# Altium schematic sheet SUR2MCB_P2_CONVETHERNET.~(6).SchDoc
size 420 x 297 mm; Scale: 1:1; Разраб.: Иванов; Обозначение документа: АБВГ.123456.001 Э3; Пров.: Петров; Утв.: Сидоров; Наименование организации: ОАО "Концерн "МПО-Гидроприбор"; Перв. применение: АБВГ.123456.000; Наименование изделия 1: Плата; Наименование изделия 2: Схема электрическая; Наименование изделия 3: принципиальная; Нач. отд.: Нач. отд.; Фамилия нач. отд.: Сидоров
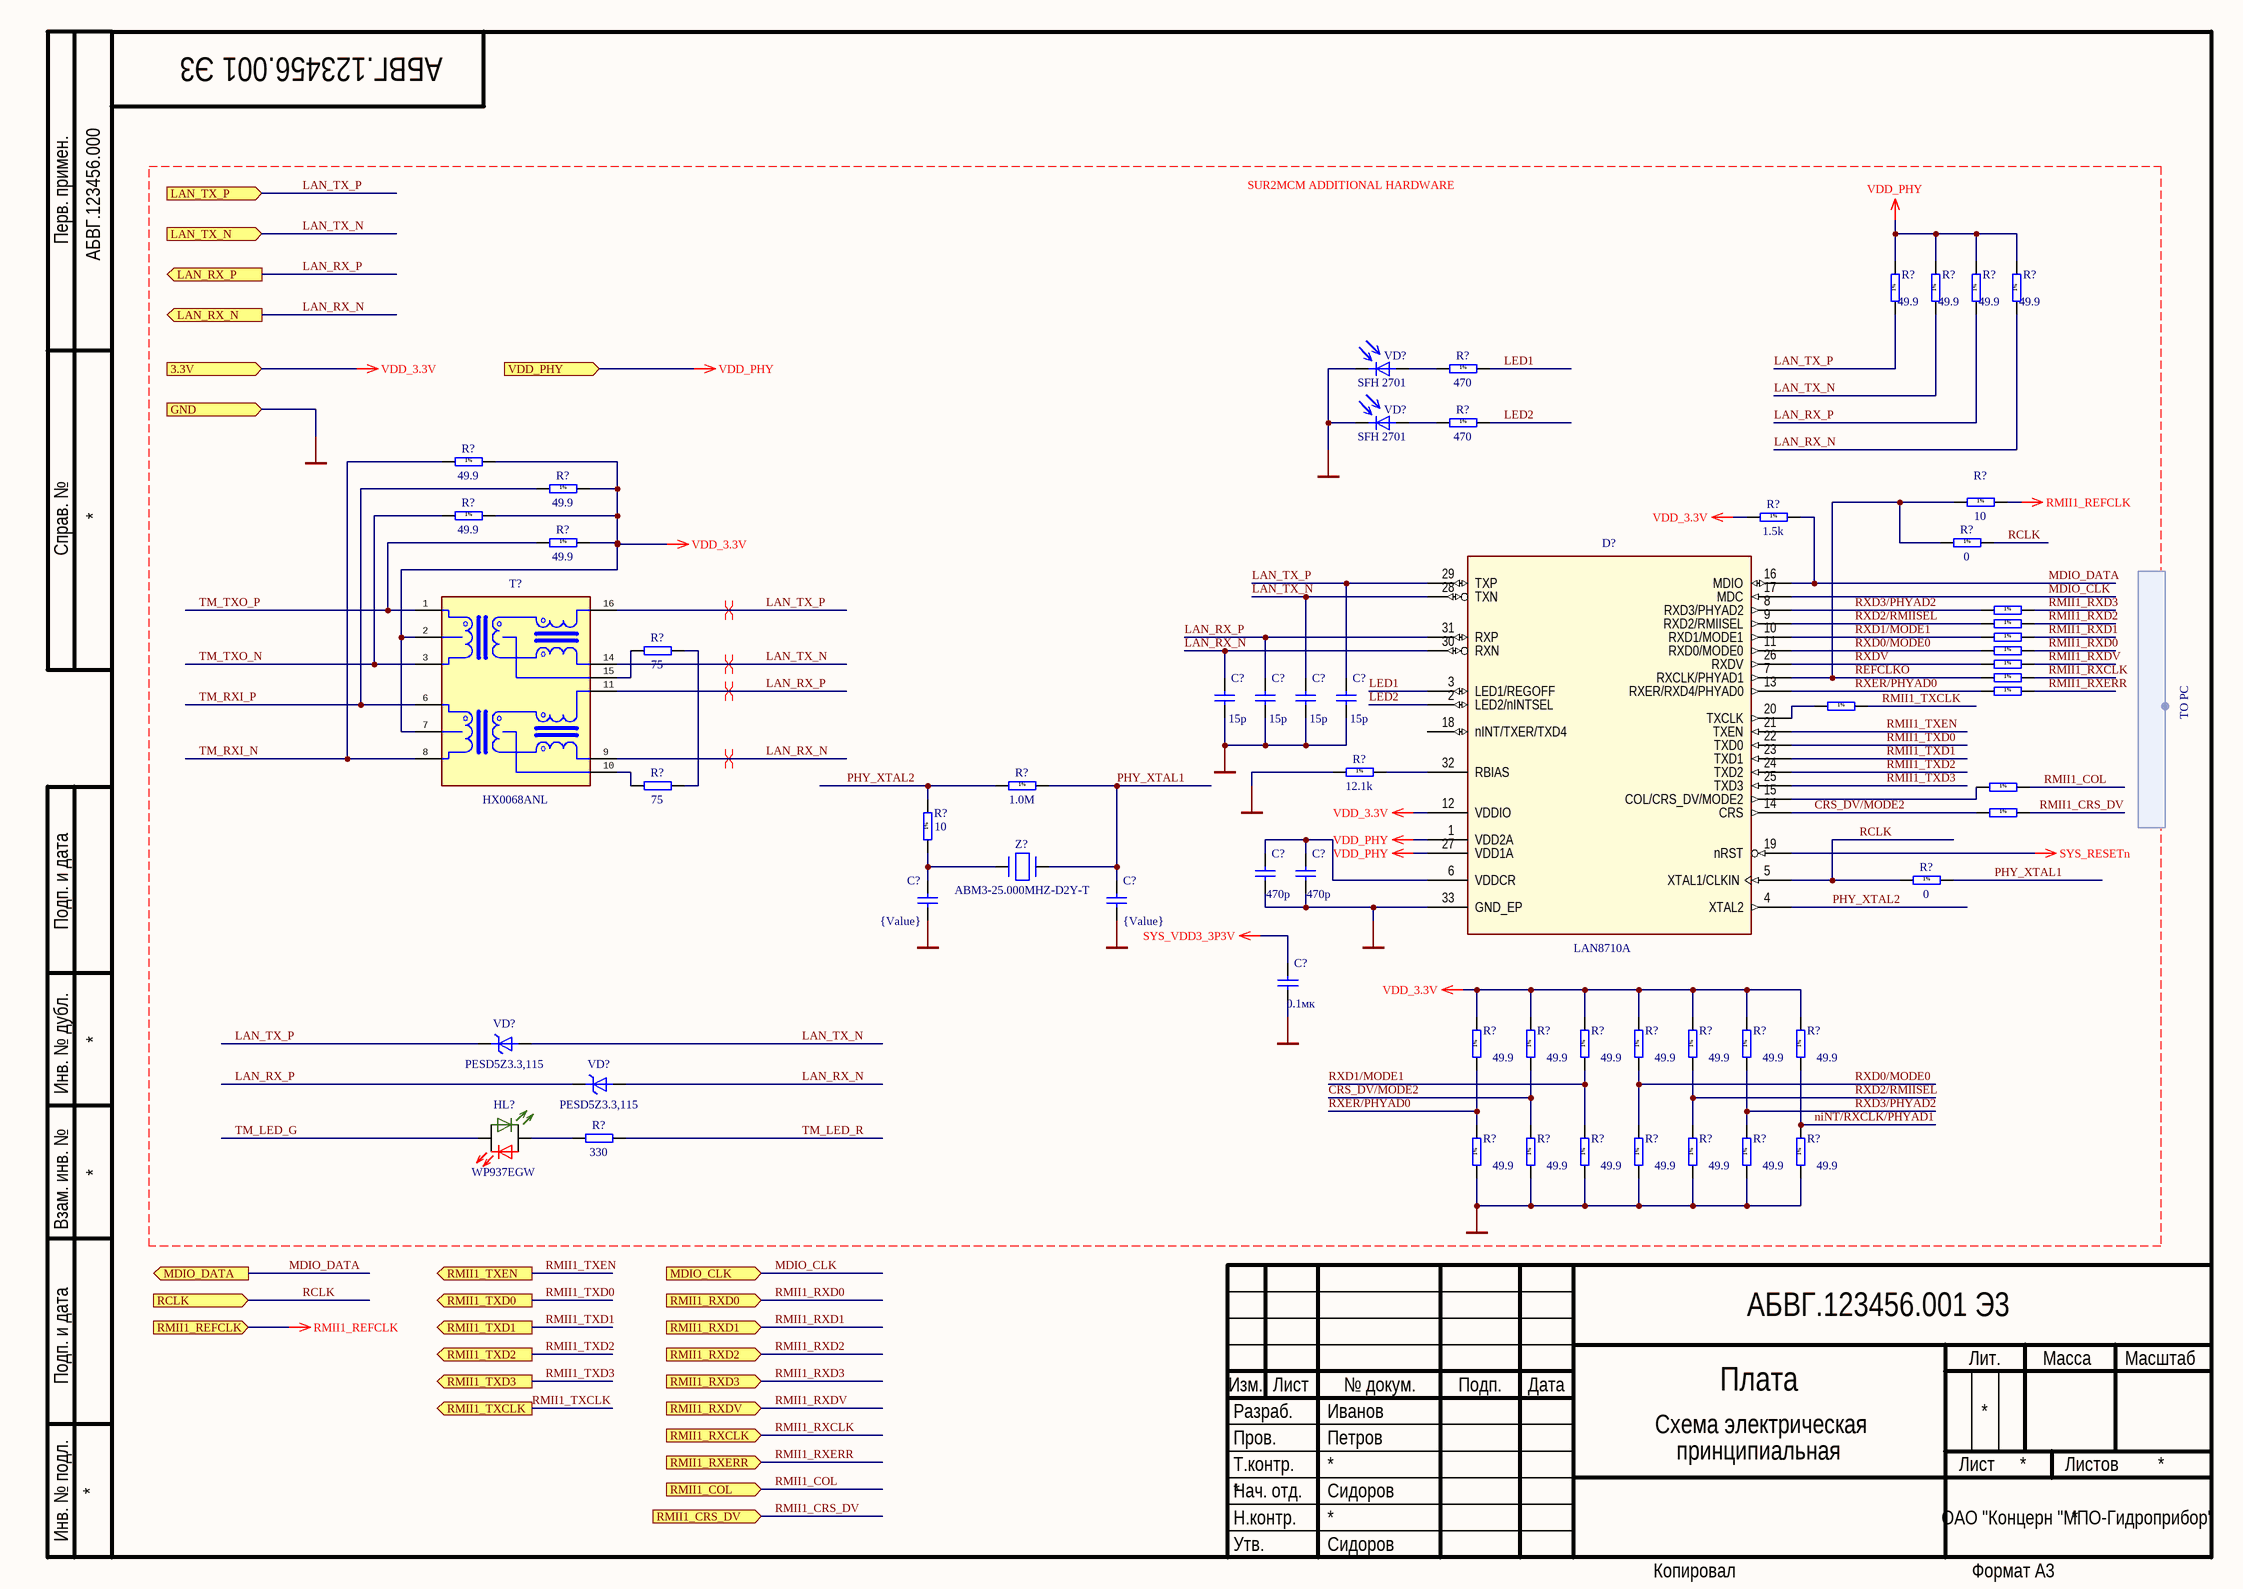
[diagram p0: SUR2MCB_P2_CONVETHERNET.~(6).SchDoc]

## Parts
(Parts that share a designator on the sheet are numbered #1, #2 ... from top to bottom, then left to right.)
C?#1  value 15p  [C0603]
C?#2  value 15p  [C0603]
C?#3  value 15p  [C0603]
C?#4  value 15p  [C0603]
C?#5  value 470p  [C0603]
C?#6  value 470p  [C0603]
C?#7  value {Value}  [C0603]
C?#8  value {Value}  [C0603]
C?#9  value 0.1мк  [C0603]
D?  value LAN8710A  [QFN-32-5X5-0.5-T]
HL?  value WP937EGW  [LED_3MM_ROUND]
R?#1  value 49.9  [R0603]
R?#2  value 49.9  [R0603]
R?#3  value 49.9  [R0603]
R?#4  value 49.9  [R0603]
R?#5  value 470  [R0603]
R?#6  value 470  [R0603]
R?#7  value 49.9  [R0603]
R?#8  value 49.9  [R0603]
R?#9  value 10  [R0603]
R?#10  value 49.9  [R0603]
R?#11  value 1.5k  [R0603]
R?#12  value 49.9  [R0603]
R?#13  value 0  [R0603]
R?#14  (no value)  [R0603]
R?#15  (no value)  [R0603]
R?#16  (no value)  [R0603]
R?#17  value 75  [R0603]
R?#18  (no value)  [R0603]
R?#19  (no value)  [R0603]
R?#20  (no value)  [R0603]
R?#21  (no value)  [R0603]
R?#22  (no value)  [R0603]
R?#23  value 12.1k  [R0603]
R?#24  value 75  [R0603]
R?#25  value 1.0М  [R0603]
R?#26  (no value)  [R0603]
R?#27  (no value)  [R0603]
R?#28  value 10  [R0603]
R?#29  value 0  [R0603]
R?#30  value 49.9  [R0603]
R?#31  value 49.9  [R0603]
R?#32  value 49.9  [R0603]
R?#33  value 49.9  [R0603]
R?#34  value 49.9  [R0603]
R?#35  value 49.9  [R0603]
R?#36  value 49.9  [R0603]
R?#37  value 330  [R0603]
R?#38  value 49.9  [R0603]
R?#39  value 49.9  [R0603]
R?#40  value 49.9  [R0603]
R?#41  value 49.9  [R0603]
R?#42  value 49.9  [R0603]
R?#43  value 49.9  [R0603]
R?#44  value 49.9  [R0603]
T?  value HX0068ANL  [HX0068ANL]
VD?#1  value SFH 2701  [SFH 2701]
VD?#2  value SFH 2701  [SFH 2701]
VD?#3  value PESD5Z3.3,115  [SOD-523]
VD?#4  value PESD5Z3.3,115  [SOD-523]
Z?  value ABM3-25.000MHZ-D2Y-T  [Crystal_2-SMD_(5.0X3.2)]

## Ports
3.3V (in), GND (in), LAN_RX_N (out), LAN_RX_P (out), LAN_TX_N (in), LAN_TX_P (in), MDIO_CLK (in), MDIO_DATA (out), RCLK (in), RMII1_COL (in), RMII1_CRS_DV (in), RMII1_REFCLK (in), RMII1_RXCLK (in), RMII1_RXD0 (in), RMII1_RXD1 (in), RMII1_RXD2 (in), RMII1_RXD3 (in), RMII1_RXDV (in), RMII1_RXERR (in), RMII1_TXCLK (out), RMII1_TXD0 (out), RMII1_TXD1 (out), RMII1_TXD2 (out), RMII1_TXD3 (out), RMII1_TXEN (out), VDD_PHY (in)

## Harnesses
TO PC: 

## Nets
GND: C?#1.1 C?#2.1 C?#3.1 C?#4.1 C?#5.1 C?#6.1 C?#7.1 C?#8.1 C?#9.1 D?.33(GND_EP) R?#23.2 R?#38.2 R?#39.2 R?#40.2 R?#41.2 R?#42.2 R?#43.2 R?#44.2 VD?#1.1(С) VD?#2.1(С) ; port GND
RMII1_REFCLK: R?#9.1 ; port RMII1_REFCLK
SYS_RESETn: D?.19(nRST)
SYS_VDD3_3P3V: C?#9.2
VDD_3.3V: D?.12(VDDIO) R?#7.1 R?#8.1 R?#10.1 R?#11.2 R?#12.1 R?#30.1 R?#31.1 R?#32.1 R?#33.1 R?#34.1 R?#35.1 R?#36.1 T?.2 T?.7 ; port 3.3V
VDD_PHY: D?.1(VDD2A) D?.27(VDD1A) R?#1.1 R?#2.1 R?#3.1 R?#4.1 ; port VDD_PHY
CRS_DV/MODE2: D?.14(CRS) R?#27.2 R?#31.2 R?#39.1
LAN_RX_N: C?#1.2 D?.30(RXN) R?#4.2 T?.9 VD?#4.2 ; port LAN_RX_N
LAN_RX_P: C?#2.2 D?.31(RXP) R?#3.2 T?.11 VD?#4.1 ; port LAN_RX_P
LAN_TX_N: C?#3.2 D?.28(TXN) R?#2.2 T?.14 VD?#3.2 ; port LAN_TX_N
LAN_TX_P: C?#4.2 D?.29(TXP) R?#1.2 T?.16 VD?#3.1 ; port LAN_TX_P
LED1: D?.3(LED1/REGOFF) R?#5.1
LED2: D?.2(LED2/nINTSEL) R?#6.1
MDIO_CLK: D?.17(MDC) ; port MDIO_CLK
MDIO_DATA: D?.16(MDIO) R?#11.1 ; port MDIO_DATA
niNT/RXCLK/PHYAD1: R?#36.2 R?#44.1
PHY_XTAL1: C?#8.2 R?#25.1 R?#29.1 Z?.2
PHY_XTAL2: D?.4(XTAL2) R?#25.2 R?#28.1
RCLK: D?.5(XTAL1/CLKIN) R?#13.1 R?#29.2 ; port RCLK
REFCLKO: D?.7(RXCLK/PHYAD1) R?#9.2 R?#13.2 R?#20.2
RMII1_COL: R?#26.1 ; port RMII1_COL
RMII1_CRS_DV: R?#27.1 ; port RMII1_CRS_DV
RMII1_RXCLK: R?#20.1 ; port RMII1_RXCLK
RMII1_RXD0: R?#18.1 ; port RMII1_RXD0
RMII1_RXD1: R?#16.1 ; port RMII1_RXD1
RMII1_RXD2: R?#15.1 ; port RMII1_RXD2
RMII1_RXD3: R?#14.1 ; port RMII1_RXD3
RMII1_RXDV: R?#19.1 ; port RMII1_RXDV
RMII1_RXERR: R?#21.1 ; port RMII1_RXERR
RMII1_TXCLK: R?#22.1 ; port RMII1_TXCLK
RMII1_TXD0: D?.22(TXD0) ; port RMII1_TXD0
RMII1_TXD1: D?.23(TXD1) ; port RMII1_TXD1
RMII1_TXD2: D?.24(TXD2) ; port RMII1_TXD2
RMII1_TXD3: D?.25(TXD3) ; port RMII1_TXD3
RMII1_TXEN: D?.21(TXEN) ; port RMII1_TXEN
RXD0/MODE0: D?.11(RXD0/MODE0) R?#18.2 R?#33.2 R?#41.1
RXD1/MODE1: D?.10(RXD1/MODE1) R?#16.2 R?#32.2 R?#40.1
RXD2/RMIISEL: D?.9(RXD2/RMIISEL) R?#15.2 R?#34.2 R?#42.1
RXD3/PHYAD2: D?.8(RXD3/PHYAD2) R?#14.2 R?#35.2 R?#43.1
RXDV: D?.26(RXDV) R?#19.2
RXER/PHYAD0: D?.13(RXER/RXD4/PHYAD0) R?#21.2 R?#30.2 R?#38.1
TM_LED_G: HL?.1
TM_LED_R: R?#37.1
TM_RXI_N: R?#7.2 T?.8
TM_RXI_P: R?#8.2 T?.6
TM_TXO_N: R?#10.2 T?.3
TM_TXO_P: R?#12.2 T?.1
NetC?#5_2: C?#5.2 C?#6.2 D?.6(VDDCR)
NetC?#7_2: C?#7.2 R?#28.2 Z?.1
NetD?_15: D?.15(COL/CRS_DV/MODE2) R?#26.2
NetD?_20: D?.20(TXCLK) R?#22.2
NetD?_32: D?.32(RBIAS) R?#23.1
NetHL?_2: HL?.2 R?#37.2
NetR?#5_2: R?#5.2 VD?#1.2(A)
NetR?#6_2: R?#6.2 VD?#2.2(A)
NetR?#17_1: R?#17.1 R?#24.1
NetR?#17_2: R?#17.2 T?.15
NetR?#24_2: R?#24.2 T?.10

Not connected (* = marked no-connect by the designer): D? 18(nINT/TXER/TXD4)

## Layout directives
differential pair: LAN_RX_N, LAN_RX_P, LAN_TX_N, LAN_TX_P

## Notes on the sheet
- SUR2MCM ADDITIONAL HARDWARE

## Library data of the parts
C?#1-C?#4 = C-0603: SMD X7R 0603 25В ±10%; ValueManufacturer: Murata Electronics; ValueManufacturerPartNumber: GCM188R71H; ValueDescription: X7R 0603 (1608)  25В  15pФ ±10%; ValueType: Ceramic Capacitor
C?#5 C?#6 = C-0603: SMD X7R 0603 25В ±10%; ValueManufacturer: Murata Electronics; ValueManufacturerPartNumber: GCM188R71H; ValueDescription: X7R 0603 (1608)  25В  470pФ ±10%; ValueType: Ceramic Capacitor
C?#7 C?#8 = C-0603: SMD X7R 0603 25В ±10%; ValueManufacturer: Murata Electronics; ValueManufacturerPartNumber: GCM188R71H; ValueDescription: X7R 0603 (1608)  25В  {Value}Ф ±10%; ValueType: Ceramic Capacitor
C?#9 = C-0603: SMD X7R 0603 25В ±10%; ValueManufacturer: Murata Electronics; ValueManufacturerPartNumber: GCM188R71H; ValueDescription: X7R 0603 (1608)  25В  0.1мкФ ±10%; ValueType: Ceramic Capacitor
D? = LAN8710A: Ethernet ICs 10/100 Ethernet XCVR w/HPAutoMDIX FlexPwr; ValueManufacturer: Texas Instruments; PowerVoltage: 1.6V~3.6V; ValueDescription: LAN8710A ethetnet приемопередатчик 1.6V~3.6V  32-VQFN(5x5); ValueType: transceiver
HL? = LED_3MM_2COLOR: LED GRN/RED DIFF 3MM ROUND; ValueManufacturer: Kingbright; PowerVoltage: 2.2V / 2V; TechSpec: Зеленый/Красный; ValueDescription: WP937EGW Свтетодиод Radial 3mm  2.2V / 2V  Зеленый/Красный; ValueType: Radial 3mm Led Diode
R?#1-R?#4 R?#7 R?#8 R?#10 R?#12 R?#30-R?#36 R?#38-R?#44 = R-0603-1%: SMD 0603 0.1Вт ±1% 75В; ValueManufacturer: Panasonic; ValueManufacturerPartNumber: ERJ-3EK; PowerVoltage: 0.1Вт 75В; ValueDescription: 0603 (1608)  0.1Вт 75В  49.9Ом ±1%; ValueType: Chip Resistor
R?#5 R?#6 = R-0603-1%: SMD 0603 0.1Вт ±1% 75В; ValueManufacturer: Panasonic; ValueManufacturerPartNumber: ERJ-3EK; PowerVoltage: 0.1Вт 75В; ValueDescription: 0603 (1608)  0.1Вт 75В  470Ом ±1%; ValueType: Chip Resistor
R?#9 R?#28 = R-0603-1%: SMD 0603 0.1Вт ±1% 75В; ValueManufacturer: Panasonic; ValueManufacturerPartNumber: ERJ-3EK; PowerVoltage: 0.1Вт 75В; ValueDescription: 0603 (1608)  0.1Вт 75В  10Ом ±1%; ValueType: Chip Resistor
R?#11 = R-0603-1%: SMD 0603 0.1Вт ±1% 75В; ValueManufacturer: Panasonic; ValueManufacturerPartNumber: ERJ-3EK; PowerVoltage: 0.1Вт 75В; ValueDescription: 0603 (1608)  0.1Вт 75В  1.5kОм ±1%; ValueType: Chip Resistor
R?#13 R?#29 = R-0603-1%: SMD 0603 0.1Вт ±1% 75В; ValueManufacturer: Panasonic; ValueManufacturerPartNumber: ERJ-3EK; PowerVoltage: 0.1Вт 75В; ValueDescription: 0603 (1608)  0.1Вт 75В  0Ом ±1%; ValueType: Chip Resistor
R?#14-R?#16 R?#18-R?#22 R?#26 R?#27 = R-0603-1%: SMD 0603 0.1Вт ±1% 75В; ValueManufacturer: Panasonic; ValueManufacturerPartNumber: ERJ-3EK; PowerVoltage: 0.1Вт 75В; ValueDescription: 0603 (1608)  0.1Вт 75В  100Ом ±1%; ValueType: Chip Resistor; Value: 100
R?#17 R?#24 = R-0603-5%: SMD 0603 0.1Вт ±5% 75В; ValueManufacturer: Panasonic; ValueManufacturerPartNumber: ERJ-3GE; PowerVoltage: 0.1Вт 75В; ValueDescription: 0603 (1608)  0.1Вт 75В  75Ом ±5%; ValueType: Chip Resistor
R?#23 = R-0603-1%: SMD 0603 0.1Вт ±1% 75В; ValueManufacturer: Panasonic; ValueManufacturerPartNumber: ERJ-3EK; PowerVoltage: 0.1Вт 75В; ValueDescription: 0603 (1608)  0.1Вт 75В  12.1kОм ±1%; ValueType: Chip Resistor
R?#25 = R-0603-1%: SMD 0603 0.1Вт ±1% 75В; ValueManufacturer: Panasonic; ValueManufacturerPartNumber: ERJ-3EK; PowerVoltage: 0.1Вт 75В; ValueDescription: 0603 (1608)  0.1Вт 75В  1.0МОм ±1%; ValueType: Chip Resistor
R?#37 = R-0603-5%: SMD 0603 0.1Вт ±5% 75В; ValueManufacturer: Panasonic; ValueManufacturerPartNumber: ERJ-3GE; PowerVoltage: 0.1Вт 75В; ValueDescription: 0603 (1608)  0.1Вт 75В  330Ом ±5%; ValueType: Chip Resistor
T? = HX0068ANL: LAN 10/100 Base-T PULSE XFMR 1CT:1CT; ValueManufacturer: Pulse Electronics Network; PowerVoltage: 350мкГн; TechSpec: Высота 2.08mm; ValueDescription: HX0068ANL Трансформатор LAN 10/100 12.70x8.81mm  350мкГн    Высота 2.08mm
VD?#1 VD?#2 = SFH 2701: PHOTODIODE PIN 820NM SMD; ValueManufacturer: OSRAM Opto Semiconductors Inc; ValueDescription: SFH 2701  2-SMD
VD?#3 VD?#4 = PESD5ZXX: TVS DIODE 3.3V 18VC SOD523; ValueManufacturer: Nexperia USA; PowerVoltage: 18V, 260kW; ValueDescription: PESD5Z3.3,115 TVS диод 18V, 260kW  SOD-523
Z? = CRYSTAL_2-SMD_ABM3: CRYSTAL 2-SMD ±20PPM 18PF 60Ohm; ValueManufacturer: Abracon LLC; ValueManufacturerPartNumber: ABM3-24.000MHZ-D2Y-T; ValueDescription: ABM3-24.000MHZ-D2Y-T  Кварцевый генератор 2-SMD (5.00x3.20mm)  ±20ppm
